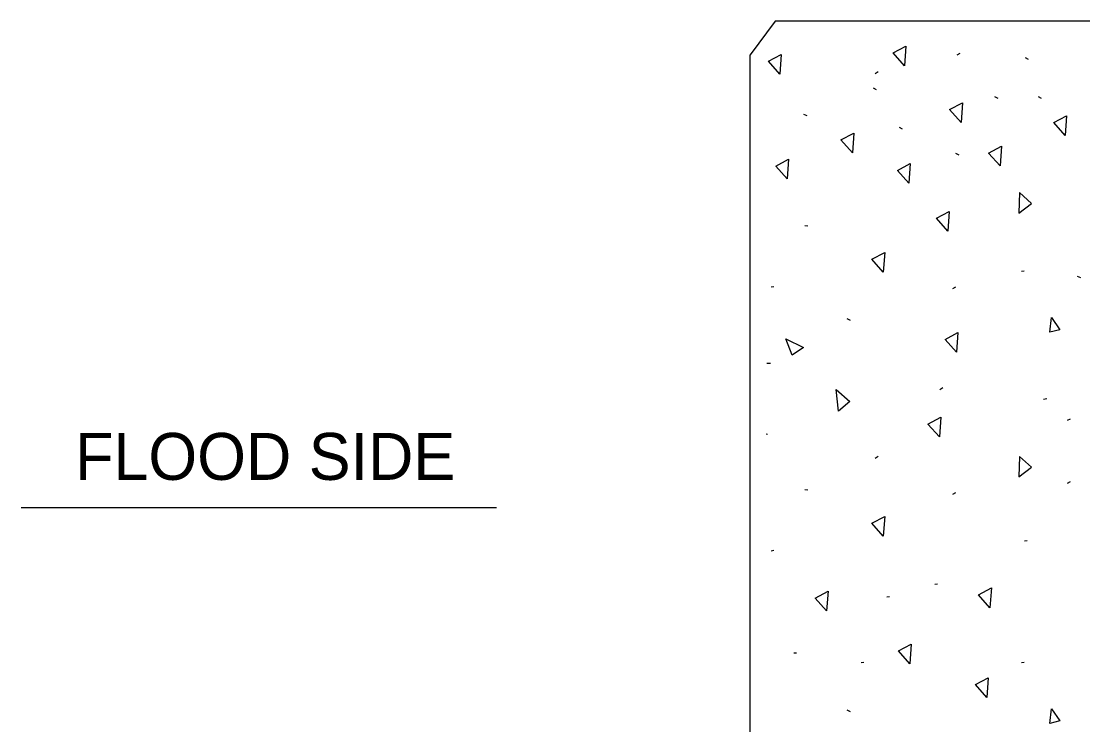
# Model space of a CAD drawing. Extents: x 22369.6 to 22389.4, y 22369.6 to 22386.
# Drawn here: x 22386.227 to 22387.546, y 22385.053 to 22385.927 of the extents above; entities that cross this region are included whole.
import ezdxf

# ---------------------------------------------------------------- set-up
doc = ezdxf.new("R2010")
doc.units = 0
for name, color, linetype in [('Level 10', 7, 'Continuous'), ('Level 3', 7, 'Continuous'), ('Level 44', 7, 'Continuous'), ('Level 7', 7, 'Continuous')]:
    doc.layers.add(name, color=color, linetype=linetype)

msp = doc.modelspace()

# ---------------------------------------------------------------- linework, layer by layer
at = {"layer": 'Level 10'}
msp.add_line((22386.8172, 22385.3226), (22386.2265, 22385.3226), dxfattribs=at)
at = {"layer": 'Level 3'}
msp.add_line((22387.1325, 22385.2704), (22387.1325, 22385.2772), dxfattribs=at)
at = {"layer": 'Level 44'}
for p, q in [((22387.3897, 22385.8854), (22387.3935, 22385.8876)), ((22387.4742, 22385.8822), (22387.4782, 22385.8802)), ((22387.2879, 22385.8624), (22387.2916, 22385.8646)), ((22387.2852, 22385.8443), (22387.2892, 22385.8423)), ((22387.4364, 22385.8335), (22387.4404, 22385.8315)), ((22387.4904, 22385.8335), (22387.4944, 22385.8315)), ((22387.1988, 22385.8119), (22387.2028, 22385.8099)), ((22387.3176, 22385.7957), (22387.3216, 22385.7937)), ((22387.3878, 22385.7633), (22387.3918, 22385.7613)), ((22387.2005, 22385.6734), (22387.2042, 22385.673)), ((22387.4696, 22385.6166), (22387.4729, 22385.6169)), ((22387.5389, 22385.6106), (22387.5429, 22385.6086)), ((22387.1585, 22385.5971), (22387.1618, 22385.5977)), ((22387.3843, 22385.5949), (22387.388, 22385.5972)), ((22387.2528, 22385.5579), (22387.2568, 22385.5559)), ((22387.1531, 22385.5025), (22387.1576, 22385.5025)), ((22387.3682, 22385.4697), (22387.372, 22385.4719)), ((22387.497, 22385.4575), (22387.5013, 22385.4583)), ((22387.5271, 22385.4314), (22387.5307, 22385.433)), ((22387.1525, 22385.4144), (22387.154, 22385.414)), ((22387.2879, 22385.3844), (22387.2916, 22385.3867)), ((22387.5271, 22385.3534), (22387.5307, 22385.3551)), ((22387.2005, 22385.3454), (22387.2042, 22385.3451)), ((22387.3843, 22385.3394), (22387.388, 22385.3416)), ((22387.1585, 22385.2692), (22387.1618, 22385.2698)), ((22387.4735, 22385.2817), (22387.4769, 22385.282)), ((22387.3621, 22385.2279), (22387.3654, 22385.2282)), ((22387.3024, 22385.212), (22387.3057, 22385.2123)), ((22387.187, 22385.1423), (22387.1903, 22385.1426)), ((22387.2705, 22385.1304), (22387.2739, 22385.1306)), ((22387.4696, 22385.1304), (22387.4729, 22385.1306)), ((22387.2528, 22385.0716), (22387.2568, 22385.0696))]:
    msp.add_line(p, q, dxfattribs=at)
for points in [[(22387.3244, 22385.8718), (22387.3102, 22385.8878), (22387.3261, 22385.8963)], [(22387.1695, 22385.8614), (22387.1552, 22385.8774), (22387.1711, 22385.8859)], [(22387.3946, 22385.8015), (22387.3803, 22385.8175), (22387.3963, 22385.826)], [(22387.5242, 22385.7853), (22387.5099, 22385.8013), (22387.5258, 22385.8098)], [(22387.2596, 22385.7637), (22387.2454, 22385.7797), (22387.2613, 22385.7882)], [(22387.4432, 22385.7474), (22387.4289, 22385.7634), (22387.4448, 22385.7719)], [(22387.1786, 22385.7312), (22387.1644, 22385.7472), (22387.1803, 22385.7557)], [(22387.3298, 22385.7258), (22387.3155, 22385.7418), (22387.3315, 22385.7503)], [(22387.4664, 22385.6888), (22387.4824, 22385.7009), (22387.4671, 22385.7144)], [(22387.3784, 22385.6664), (22387.3641, 22385.6824), (22387.38, 22385.6909)], [(22387.298, 22385.6154), (22387.2838, 22385.6314), (22387.2997, 22385.6399)], [(22387.5048, 22385.5409), (22387.5071, 22385.5592), (22387.5174, 22385.5439)], [(22387.3891, 22385.5159), (22387.3749, 22385.5319), (22387.3908, 22385.5404)], [(22387.1846, 22385.5123), (22387.1767, 22385.5327), (22387.1988, 22385.5219)], [(22387.2393, 22385.4695), (22387.2564, 22385.4546), (22387.2422, 22385.4427)], [(22387.3677, 22385.4107), (22387.3535, 22385.4267), (22387.3694, 22385.4352)], [(22387.4664, 22385.3609), (22387.4824, 22385.3729), (22387.4671, 22385.3865)], [(22387.298, 22385.2875), (22387.2838, 22385.3035), (22387.2997, 22385.312)], [(22387.2276, 22385.1945), (22387.2134, 22385.2105), (22387.2293, 22385.219)], [(22387.4306, 22385.1985), (22387.4164, 22385.2145), (22387.4323, 22385.223)], [(22387.3311, 22385.1288), (22387.3169, 22385.1448), (22387.3328, 22385.1533)], [(22387.4266, 22385.0869), (22387.4124, 22385.1029), (22387.4283, 22385.1114)], [(22387.5048, 22385.0547), (22387.5071, 22385.0729), (22387.5174, 22385.0577)]]:
    msp.add_lwpolyline(points, close=True, dxfattribs=at)
at = {"layer": 'Level 7'}
for p, q in [((22387.1637, 22385.9272), (22387.1325, 22385.8855)), ((22387.6012, 22385.9272), (22387.1637, 22385.9272)), ((22387.1325, 22384.4772), (22387.1325, 22385.8855))]:
    msp.add_line(p, q, dxfattribs=at)

# ---------------------------------------------------------------- texts
at = {"layer": 'Level 10'}
msp.add_text('FLOOD SIDE', height=0.05833, dxfattribs=at).set_placement((22386.2935, 22385.3573))

doc.saveas('drawing.dxf')
